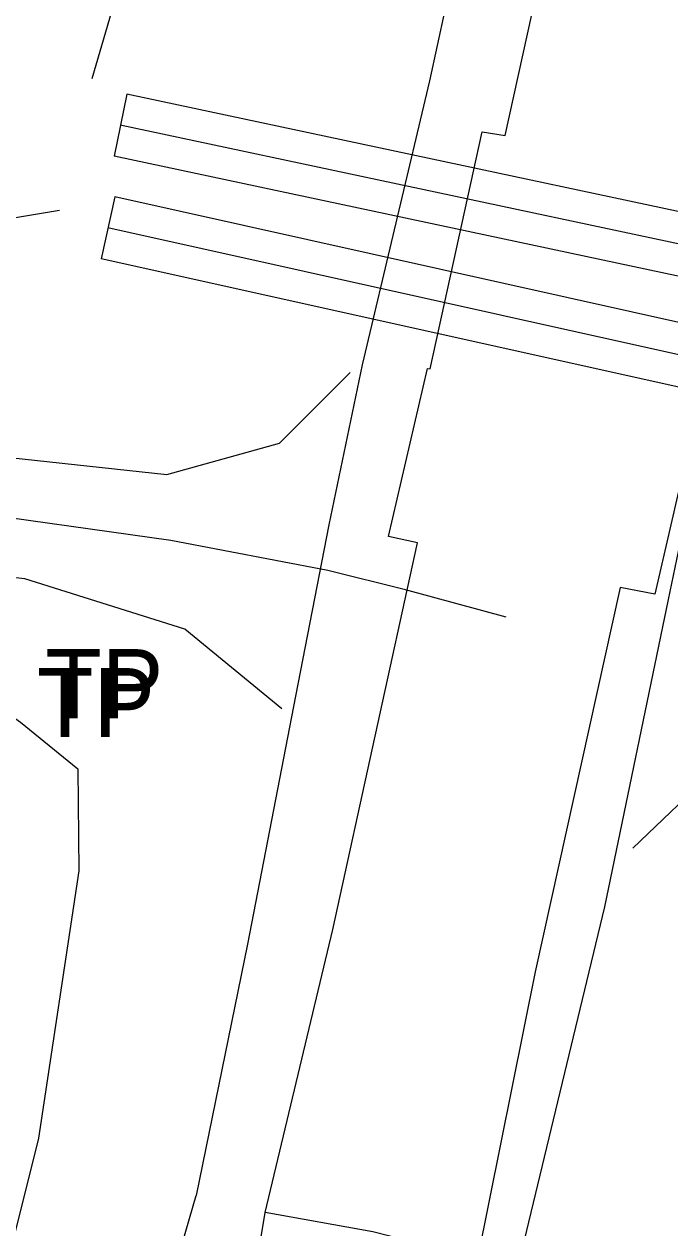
# Model space of a CAD drawing. Extents: x 14105231 to 14123593, y 8636972 to 8671693.
# Drawn here: x 14108503.3 to 14108578.1, y 8642842.8 to 8642982.2 of the extents above; entities that cross this region are included whole.
import ezdxf

# ---------------------------------------------------------------- set-up
doc = ezdxf.new("R2010")
doc.units = 0
for name, color, linetype in [('PhoDrainageArrow', 7, 'Continuous'), ('PhoEdgeRoadPaved', 7, 'Continuous'), ('PhoEdgeShoulderPaved', 7, 'Continuous'), ('SurCulvert', 7, 'Continuous'), ('SurDrainageArrowUp', 7, 'Continuous'), ('SurEdgeEntranceUnpaved', 7, 'Continuous'), ('SurEdgeRoadPaved', 7, 'Continuous'), ('SurEdgeShoulderPaved', 7, 'Continuous'), ('SurEntranceCL', 7, 'Continuous'), ('SurUtilityCells', 7, 'Continuous')]:
    doc.layers.add(name, color=color, linetype=linetype)

msp = doc.modelspace()

# ---------------------------------------------------------------- linework, layer by layer
at = {"layer": 'PhoDrainageArrow'}
msp.add_lwpolyline([(14108500.42, 8642903.14), (14108502.91, 8642901.35), (14108509.58, 8642895.95), (14108509.68, 8642884.14), (14108504.99, 8642853.16), (14108497.39, 8642822.85), (14108490.16, 8642789.86), (14108481.16, 8642750.48), (14108471.71, 8642704.4), (14108462.23, 8642663.39), (14108451.43, 8642613.28), (14108443.87, 8642578.53), (14108434.48, 8642535.09), (14108420.14, 8642475.56), (14108408.71, 8642424.21), (14108399.22, 8642377.7)], dxfattribs=at)
at = {"layer": 'PhoEdgeRoadPaved'}
msp.add_lwpolyline([(14108408.22, 8642282.74), (14108416.84, 8642322.21), (14108425.36, 8642361.25), (14108434.24, 8642400.66), (14108442.83, 8642439.93), (14108451.29, 8642479.08), (14108459.88, 8642518.37), (14108468.46, 8642557.78), (14108477.03, 8642597.16), (14108485.84, 8642636.18), (14108494.55, 8642675.4), (14108503.19, 8642714.56), (14108511.84, 8642753.93), (14108520.77, 8642794.08), (14108529.32, 8642832.9), (14108531.26, 8642844.56)], dxfattribs=at)
at = {"layer": 'PhoEdgeShoulderPaved'}
msp.add_lwpolyline([(14108399.8, 8642284.57), (14108408.41, 8642324.04), (14108416.94, 8642363.1), (14108425.82, 8642402.52), (14108434.4, 8642441.75), (14108442.86, 8642480.9), (14108451.45, 8642520.19), (14108460.03, 8642559.6), (14108468.6, 8642599.01), (14108477.43, 8642638.05), (14108485.61, 8642677.31), (14108494.04, 8642716.62), (14108502.86, 8642756.12), (14108511.33, 8642796.67), (14108519.94, 8642835.08), (14108523.26, 8642846.52)], dxfattribs=at)
at = {"layer": 'SurCulvert'}
for p, q in [((14108515.22, 8642974.07), (14108513.75, 8642966.89)), ((14108622.08, 8642951.34), (14108515.22, 8642974.07)), ((14108621.29, 8642947.76), (14108514.48, 8642970.48)), ((14108620.5, 8642944.18), (14108513.75, 8642966.89)), ((14108513.83, 8642962.17), (14108512.25, 8642955.01)), ((14108619.3, 8642938.71), (14108513.83, 8642962.17)), ((14108618.52, 8642935.13), (14108513.04, 8642958.59)), ((14108617.73, 8642931.55), (14108512.25, 8642955.01))]:
    msp.add_line(p, q, dxfattribs=at)
at = {"layer": 'SurDrainageArrowUp'}
for points in [[(14108511.22, 8642975.87), (14108520.99, 8643009.26), (14108528.41, 8643041.83)], [(14108507.44, 8642960.61), (14108487.41, 8642957.26), (14108441.71, 8642963.51)]]:
    msp.add_lwpolyline(points, dxfattribs=at)
at = {"layer": 'SurEdgeEntranceUnpaved'}
for points in [[(14108438.53, 8642938.07), (14108473.87, 8642934.41), (14108501.68, 8642932.01), (14108519.88, 8642930.04), (14108532.91, 8642933.65), (14108541.09, 8642941.84)], [(14108533.17, 8642902.89), (14108521.96, 8642912.13), (14108503.41, 8642917.93), (14108474.74, 8642921.11), (14108438.01, 8642924.81)], [(14108611.5, 8642892.75), (14108596.23, 8642895.96), (14108583.42, 8642895.93), (14108573.84, 8642886.76)]]:
    msp.add_lwpolyline(points, dxfattribs=at)
at = {"layer": 'SurEdgeRoadPaved'}
for points in [[(14108531.26, 8642844.56), (14108539.08, 8642877.34), (14108548.9, 8642922.11), (14108545.53, 8642922.84), (14108550.03, 8642942.31), (14108550.37, 8642942.26), (14108556.37, 8642969.7), (14108559.05, 8642969.27), (14108569.88, 8643018.52)], [(14108590.94, 8642983.09), (14108586.9, 8642963.63), (14108585.69, 8642963.9), (14108579.72, 8642935.87), (14108580.83, 8642935.59), (14108576.37, 8642916.18), (14108572.36, 8642916.94), (14108562.53, 8642872.43), (14108555.82, 8642839.24), (14108543.71, 8642842.34), (14108531.26, 8642844.56)]]:
    msp.add_lwpolyline(points, dxfattribs=at)
at = {"layer": 'SurEdgeShoulderPaved'}
for points in [[(14108577.69, 8643103.84), (14108568.11, 8643059.02), (14108559.17, 8643016.57), (14108550.29, 8642975.6), (14108542.48, 8642942.71), (14108538.64, 8642924.19), (14108534.76, 8642904.37), (14108529.2, 8642875.63), (14108523.26, 8642846.52)], [(14108560.51, 8642838.14), (14108570.57, 8642879.98), (14108577.94, 8642915.57), (14108588, 8642963.71), (14108588, 8642963.73), (14108592.17, 8642982.51), (14108601.43, 8643029.06), (14108611.53, 8643075.66), (14108615.55, 8643095.95)]]:
    msp.add_lwpolyline(points, dxfattribs=at)
at = {"layer": 'SurEntranceCL'}
msp.add_lwpolyline([(14108559.15, 8642913.51), (14108547.49, 8642916.68), (14108538.51, 8642918.9), (14108520.34, 8642922.39), (14108494.47, 8642926.03), (14108462.77, 8642929.48), (14108432.09, 8642932.1), (14108385.29, 8642936.46)], dxfattribs=at)

# ---------------------------------------------------------------- texts
at = {"layer": 'SurUtilityCells'}
for p in [(14108505.8, 8642901.81), (14108504.82, 8642899.61)]:
    msp.add_text('TP', height=7.998, dxfattribs=at).set_placement(p)

doc.saveas('drawing.dxf')
